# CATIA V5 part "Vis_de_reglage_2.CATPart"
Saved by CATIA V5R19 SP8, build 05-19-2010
Part number: Vis_de_reglage_2
Bounding box of the stored display mesh (mm): x 50 to 81.435, y -610.988 to -590.988, z 1340.785 to 1358.106
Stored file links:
  G:\EU_thinkMotion\CFAO_2010\MMS_groupe2\MMS_groupe2\OK\nrosalie\nrosalie_cfao_support_d_arme_legere_final\Vis_de_reglage_2.CATPart
  G:\EU_thinkMotion\CFAO_2010\MMS_groupe2\MMS_groupe2\OK\nrosalie\nrosalie_cfao_support_d_arme_legere_final\nrosalie_Support_d_arme_legere.CATProduct
  G:\EU_thinkMotion\CFAO_2010\MMS_groupe2\MMS_groupe2\OK\nrosalie\nrosalie_cfao_support_d_arme_legere_final\Bras.CATPart
  G:\EU_thinkMotion\CFAO_2010\MMS_groupe2\MMS_groupe2\OK\nrosalie\nrosalie_cfao_support_d_arme_legere_final\Arme.CATPart
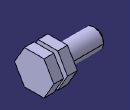
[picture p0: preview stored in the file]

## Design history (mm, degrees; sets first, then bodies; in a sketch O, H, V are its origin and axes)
Set1
  Sketch1 on face of DatumSurface1, origin (69.4353, 0, 0), H (0, 1, 0), V (0, 0, 1)
    circle A1 centre (-600.9884, 1349.4457) radius 5
    reference projected circle E1 centre (-600.9884, 1349.4457) radius 5 from edge of DatumCurve1
    coincidence: E1 A1
Set2
  DatumSurface1: linked copy from another document
  DatumCurve1: linked copy from another document
  DatumSurface2: linked copy from another document
Body1 (main body)
  Pad1: profile Sketch1, direction (1, 0, 0), up to face of DatumSurface2, opposite side length -7
  Chamfer1: length 1, angle 45, on end face of Pad1
  Sketch2 on start face of Pad1, origin (76.4353, 0, 0), H (0, 1, 0), V (0, 0, 1)
    construction circle A1 centre (-600.9884, 1349.4457) radius 0
    line L1 (-600.9884, 1349.4457) -> (-600.9884, 1349.4457)
    line L2 (-600.9884, 1349.4457) -> (-600.9884, 1349.4457)
    line L3 (-600.9884, 1349.4457) -> (-600.9884, 1349.4457)
    line L4 (-600.9884, 1349.4457) -> (-600.9884, 1349.4457)
    line L5 (-600.9884, 1349.4457) -> (-600.9884, 1349.4457)
    line L6 (-600.9884, 1349.4457) -> (-600.9884, 1349.4457)
    construction line L7 (-624.0878, 1349.4457) -> (-549.6786, 1349.4457)
    axis line L8 (-598.9778, 1352.9281) -> (-586.6381, 1374.3011)
    construction circle A2 centre (-600.9884, 1349.4457) radius 10
    point P15 (-600.9884, 1349.4457)
    line L9 (-610.9884, 1349.4457) -> (-605.9884, 1358.106)
    point P16 (-610.9884, 1349.4457)
    point P17 (-605.9884, 1358.106)
    line L10 (-605.9884, 1358.106) -> (-595.9884, 1358.106)
    point P18 (-595.9884, 1358.106)
    line L11 (-595.9884, 1358.106) -> (-590.9884, 1349.4457)
    point P19 (-590.9884, 1349.4457)
    line L12 (-590.9884, 1349.4457) -> (-595.9884, 1340.7855)
    point P20 (-595.9884, 1340.7855)
    line L13 (-595.9884, 1340.7855) -> (-605.9884, 1340.7855)
    point P21 (-605.9884, 1340.7855)
    line L14 (-605.9884, 1340.7855) -> (-610.9884, 1349.4457)
    reference projected circle E1 centre (-600.9884, 1349.4457) radius 5 from edge [face of Pad1 from Sketch1.A1 | start face of Pad1]
    angle L8 L7 = 60
    radius A2 = 10
    coincidence: P16 A2, P17 A2, P19 A2, P20 A2, P21 A2, P15 L7, P15 L8, P18 L8, P18 A2, P19 L7, P16 L7
    horizontal: L10 H, L13 H, L7 H
    concentricity: E1 A2
    symmetry: L13 L10 L7
  Pad2: profile Sketch2, direction (1, 0, 0), length 5
  Sketch3 on face of DatumSurface1, origin (69.4353, 0, 0), H (0, 1, 0), V (0, 0, 1)
  Pad3: profile Sketch3, direction (1, 0, 0), length 5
